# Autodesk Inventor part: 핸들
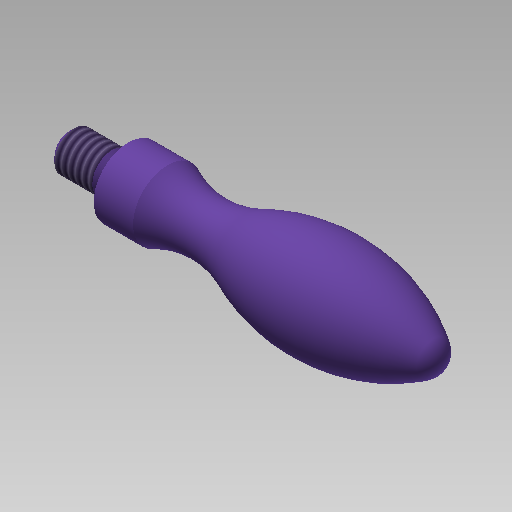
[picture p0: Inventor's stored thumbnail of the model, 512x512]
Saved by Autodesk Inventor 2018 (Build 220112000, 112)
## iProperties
Created: 2019-10
Part Number: 핸들
Material: 스테인리스강
Document SubType Name: Modeling
Designer: mduedu
Density: 1 g/cm^3
Appearance: 보라색
Author: mduedu
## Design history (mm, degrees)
sketch "스케치1"
  geometry: L1 (0, 0)-(0, 2); L2 (0, 2)-(4.35, 2); L3 (6, 1.45)-(6, 3.5); L4 (6, 3.5)-(10, 3.5); L5 (0, 0)-(38, 0); L6 (4.9, 1.45)-(6, 1.45); L7 (4.9, 1.45)-(4.35, 2); A1 r 9.5 centre (14.243, 12) between (10, 3.5) and (18.07, 3.305); A2 r 20 centre (26.128, -15) between (37.049, 1.754) and (18.07, 3.305); A3 r 2.094 centre (35.906, 0) between (38, 0) and (37.049, 1.754)
  constraints: 14 end point, 6 point on circle, 3 centre point, 3 parallel, 2 tangent, 1 perpendicular, 1 point on line, 1 vertical
  dimensions: "d1" = 4 diameter of L2 L5; "d2" = 7 diameter of L4 L5; "d4" = 4 distance of L3.end L4.end; "d5" = 5 dimension on A1 L5; "d6" = 9.5 radius of A1; "d7" = 10 dimension on A2 L5; "d8" = 20 radius of A2; "d15" = 6 distance between parallel lines of L1 L3; "d16" = 38 distance from line of L5.end L1; "d17" = 2.9 diameter of L6 L5 (computed from d1); "d19" = 1.1 distance of L6.start L3.start; "d20" = 135 deg angle of L7 L6
revolve "회전1" sketch "스케치1" stored, may be unused: angle "d9" = 90 deg
feature "스레드1" dims "d10" = 5, "d11" = 0
chamfer "모따기1" distance "d12" = 0.5; stored, may be unused: second distance "d13" = 2, angle "d14" = 45 deg
fillet "모깎기1" dims "d21" = 0.4
node "솔리드1"
